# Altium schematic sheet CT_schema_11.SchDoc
size 274 x 160 mm
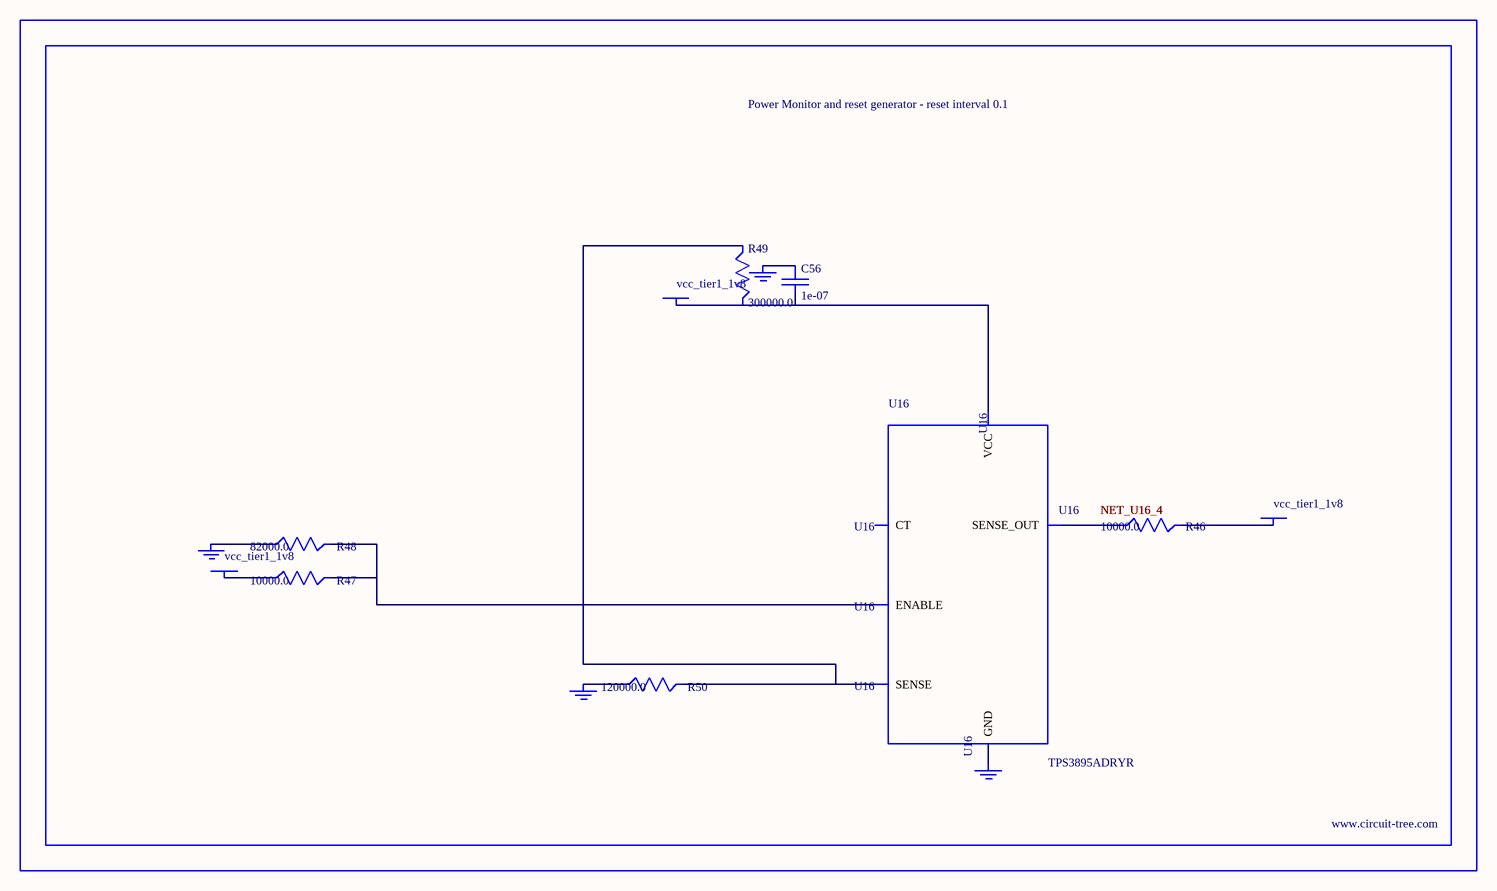
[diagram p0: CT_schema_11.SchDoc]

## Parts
BORDER10  (no value)
C56  1e-07  [C0402]
GND_INSTANCE_10_0  (no value)
GND_INSTANCE_10_1  (no value)
GND_INSTANCE_10_2  (no value)
GND_INSTANCE_10_3  (no value)
POWER_INSTANCE_10_0  vcc_tier1_1v8
POWER_INSTANCE_10_1  vcc_tier1_1v8
POWER_INSTANCE_10_2  vcc_tier1_1v8
R46  10000.0  [R0603]
R47  10000.0  [R0603]
R48  82000.0  [R0603]
R49  300000.0  [R0603]
R50  120000.0  [R0603]
U16  TPS3895ADRYR  [SON-6]

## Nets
NetC56_1: C56.1 GND_INSTANCE_10_2.0(GND)
NetC56_2: C56.2 POWER_INSTANCE_10_2.0(PWR) R49.2 U16.6(VCC)
NetGND_INSTANCE_10_0_0: GND_INSTANCE_10_0.0(GND) R48.1
NetGND_INSTANCE_10_1_0: GND_INSTANCE_10_1.0(GND) R50.1
NetGND_INSTANCE_10_3_0: GND_INSTANCE_10_3.0(GND) U16.2(GND)
NetPOWER_INSTANCE_10_0_0: POWER_INSTANCE_10_0.0(PWR) R47.1
NetPOWER_INSTANCE_10_1_0: POWER_INSTANCE_10_1.0(PWR) R46.2
NetR46_1: R46.1 U16.4(SENSE_OUT)
NetR47_2: R47.2 R48.2 U16.1(ENABLE)
NetR49_1: R49.1 R50.2 U16.3(SENSE)

Not connected (* = marked no-connect by the designer): U16 5(CT)

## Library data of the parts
BORDER10 = BORDER_PAGE10
C56 = C0402C104K3RACTU
GND_INSTANCE_10_0-GND_INSTANCE_10_3 = GND
POWER_INSTANCE_10_0-POWER_INSTANCE_10_2 = PWR
R46 R47 = RC0603JR-0710KL
R48 = RC0603JR-0782KL
R49 = RC0603JR-07300KL
R50 = RC0603JR-07120KL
